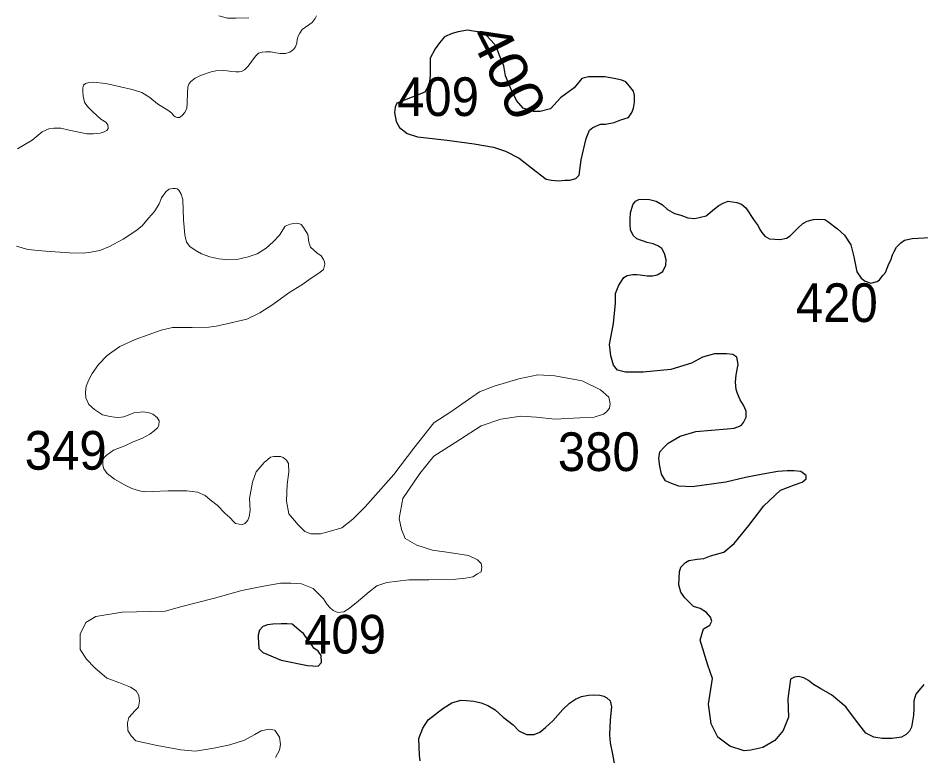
# Model space of a CAD drawing. Extents: x 445.4 to 500, y 8728.7 to 8784.
# Drawn here: x 490.993 to 494.73, y 8731.487 to 8734.54 of the extents above; entities that cross this region are included whole.
import ezdxf
from ezdxf.enums import TextEntityAlignment as Align

# ---------------------------------------------------------------- set-up
doc = ezdxf.new("R2010")
doc.units = 0
doc.header["$LTSCALE"] = 0.064
doc.layers.add('1', color=7, linetype='Continuous', lineweight=25)
doc.layers.add('2', color=7, linetype='Continuous', lineweight=13)
doc.layers.add('21', color=7, linetype='Continuous')
doc.layers.add('61', color=7, linetype='Continuous')

msp = doc.modelspace()

# ---------------------------------------------------------------- linework, layer by layer
at = {"layer": '1'}
for points in [[(492.7687, 8734.0344), (492.881, 8734.0204), (492.9618, 8734.0064), (493.0109, 8733.9889), (493.0671, 8733.9609), (493.1373, 8733.9048), (493.1794, 8733.8733), (493.2005, 8733.8698), (493.232, 8733.8663), (493.2566, 8733.8698), (493.2777, 8733.8698), (493.3022, 8733.8768), (493.3163, 8733.8908), (493.3233, 8733.9539), (493.3444, 8734.0414), (493.3584, 8734.0765), (493.3725, 8734.087), (493.404, 8734.101), (493.4251, 8734.101), (493.4602, 8734.108), (493.4883, 8734.1185), (493.5199, 8734.129), (493.5339, 8734.15), (493.5409, 8734.1676), (493.5444, 8734.1921), (493.5444, 8734.2201), (493.5409, 8734.2376), (493.5234, 8734.2586), (493.5093, 8734.2762), (493.4918, 8734.2832), (493.4602, 8734.2902), (493.4216, 8734.2972), (493.3935, 8734.2972), (493.3549, 8734.2972), (493.3268, 8734.2902), (493.2952, 8734.2516), (493.2391, 8734.2096), (493.1969, 8734.1641), (493.1548, 8734.1535), (493.1267, 8734.1535), (493.0846, 8734.1676), (493.0565, 8734.1991), (493.0355, 8734.2411), (493.0109, 8734.3007), (493.0039, 8734.3427), (492.9863, 8734.3848), (492.9723, 8734.4233), (492.9512, 8734.4478), (492.9302, 8734.4688), (492.8986, 8734.4829), (492.8775, 8734.4864), (492.853, 8734.4899), (492.8143, 8734.4829), (492.7898, 8734.4759), (492.7582, 8734.4618), (492.7371, 8734.4373), (492.7196, 8734.4128), (492.6985, 8734.3743), (492.6985, 8734.3497), (492.6985, 8734.3042), (492.695, 8734.2657), (492.6775, 8734.2341), (492.6248, 8734.2131), (492.5616, 8734.1886), (492.5546, 8734.1711), (492.5511, 8734.15), (492.5581, 8734.1115), (492.5722, 8734.087), (492.6037, 8734.0625), (492.6459, 8734.0484), (492.6845, 8734.0449)], [(492.1929, 8731.968), (492.1745, 8731.9938), (492.1649, 8732.0015), (492.1284, 8732.0323), (492.1072, 8732.0342), (492.0822, 8732.0342), (492.0475, 8732.0323), (492.0263, 8732.0304), (492.0058, 8732.0224), (491.9926, 8732.0084), (491.9878, 8731.9872), (491.987, 8731.9788), (491.9898, 8731.9322), (492.0062, 8731.9156), (492.0825, 8731.8837), (492.1919, 8731.861), (492.2361, 8731.8591), (492.2487, 8731.8741), (492.2475, 8731.9033), (492.2352, 8731.9204), (492.2176, 8731.9332), (492.2112, 8731.9443)]]:
    msp.add_lwpolyline(points, close=True, dxfattribs=at)
for points in [[(493.4805, 8733.4354), (493.5, 8733.4668), (493.5149, 8733.4757), (493.5373, 8733.4787), (493.5538, 8733.4787), (493.5687, 8733.4772), (493.5971, 8733.4742), (493.621, 8733.4742), (493.6389, 8733.4772), (493.6613, 8733.4921), (493.6748, 8733.5175), (493.6763, 8733.5398), (493.6688, 8733.5667), (493.6583, 8733.5861), (493.6419, 8733.598), (493.6225, 8733.6054), (493.5971, 8733.6114), (493.5538, 8733.6263), (493.5388, 8733.6412), (493.5283, 8733.6636), (493.5269, 8733.686), (493.5269, 8733.7098), (493.5283, 8733.7337), (493.5373, 8733.768), (493.5495, 8733.7822), (493.5629, 8733.7896), (493.5883, 8733.7911), (493.6063, 8733.7896), (493.6347, 8733.7822), (493.6601, 8733.7673), (493.681, 8733.7479), (493.7109, 8733.7315), (493.7363, 8733.724), (493.7661, 8733.7136), (493.7945, 8733.7106), (493.8408, 8733.7225), (493.8752, 8733.7509), (493.8931, 8733.7643), (493.9111, 8733.7747), (493.932, 8733.7822), (493.9679, 8733.7777), (493.9873, 8733.7703), (494.0052, 8733.7553), (494.0396, 8733.7031), (494.056, 8733.6808), (494.0635, 8733.6659), (494.0724, 8733.6524), (494.0844, 8733.6375), (494.1038, 8733.6271), (494.1471, 8733.6241), (494.174, 8733.6301), (494.189, 8733.639), (494.2069, 8733.6569), (494.2204, 8733.6703), (494.2413, 8733.6897), (494.2592, 8733.7002), (494.2861, 8733.7061), (494.304, 8733.7076), (494.3324, 8733.7061), (494.3444, 8733.6987), (494.3843, 8733.6686), (494.4142, 8733.6418), (494.4396, 8733.6015), (494.453, 8733.5523), (494.465, 8733.4903), (494.4829, 8733.4634), (494.4994, 8733.4515), (494.5233, 8733.444), (494.5487, 8733.45), (494.5591, 8733.4574), (494.5726, 8733.4753), (494.583, 8733.4873), (494.598, 8733.5231), (494.6054, 8733.538), (494.6129, 8733.5603), (494.6189, 8733.5738), (494.6293, 8733.5917), (494.6473, 8733.6096), (494.6622, 8733.6215), (494.6936, 8733.6275), (494.7683, 8733.6319)], [(493.9249, 8733.1511), (493.8757, 8733.1511), (493.8266, 8733.1374), (493.7801, 8733.1129), (493.6954, 8733.0856), (493.5806, 8733.0747), (493.5068, 8733.0747), (493.474, 8733.0829), (493.4576, 8733.1047), (493.4467, 8733.1429), (493.4413, 8733.1893), (493.4576, 8733.2765), (493.4657, 8733.3601), (493.4657, 8733.401), (493.4805, 8733.4354)], [(494.7425, 8731.7837), (494.7097, 8731.7428), (494.7015, 8731.7155), (494.7015, 8731.6828), (494.6988, 8731.6555), (494.696, 8731.6309), (494.6906, 8731.6064), (494.6824, 8731.59), (494.6687, 8731.5764), (494.6496, 8731.5655), (494.6113, 8731.56), (494.5703, 8731.56), (494.5348, 8731.5655), (494.502, 8731.5818), (494.4637, 8731.6309), (494.42, 8731.6909), (494.3599, 8731.74), (494.3162, 8731.7646), (494.2861, 8731.7837), (494.2643, 8731.8), (494.2451, 8731.8109), (494.2233, 8731.8164), (494.2069, 8731.8137), (494.1905, 8731.8055), (494.1795, 8731.7237), (494.1823, 8731.6473), (494.1604, 8731.5927), (494.1249, 8731.5518), (494.0757, 8731.5218), (494.0265, 8731.5109), (493.9992, 8731.5082), (493.9391, 8731.5273), (493.8899, 8731.5655), (493.8626, 8731.62), (493.8516, 8731.7018), (493.868, 8731.8082), (493.8489, 8731.8628), (493.8161, 8731.9664), (493.8298, 8732.0128), (493.8571, 8732.0291), (493.8653, 8732.0455), (493.8598, 8732.0619), (493.8434, 8732.081), (493.8161, 8732.0973), (493.7888, 8732.1055), (493.7533, 8732.141), (493.7369, 8732.1655), (493.7287, 8732.1955), (493.7309, 8732.2492), (493.7363, 8732.2683), (493.7555, 8732.2874), (493.7691, 8732.2956), (493.8046, 8732.3011), (493.832, 8732.3038), (493.8593, 8732.3147), (493.9139, 8732.3311), (493.9577, 8732.3665), (494.0178, 8732.4402), (494.0806, 8732.522), (494.149, 8732.5874), (494.2063, 8732.6093), (494.2391, 8732.6202), (494.2555, 8732.6338), (494.2555, 8732.6474), (494.2337, 8732.6638), (494.2036, 8732.6665), (494.1763, 8732.6665), (494.138, 8732.6638), (494.0752, 8732.6529), (494.0041, 8732.6393), (493.9221, 8732.6202), (493.7828, 8732.6011), (493.7281, 8732.6038), (493.6981, 8732.6147), (493.6735, 8732.6256), (493.6571, 8732.6529), (493.6489, 8732.6856), (493.6461, 8732.7184), (493.6489, 8732.7456), (493.668, 8732.7647), (493.6844, 8732.7811), (493.7336, 8732.8102), (493.7992, 8732.8292), (493.9277, 8732.8402), (493.9577, 8732.8429), (493.9796, 8732.8511), (493.9878, 8732.8565), (493.996, 8732.8674), (494.0069, 8732.8892), (494.0069, 8732.9138), (493.996, 8732.9383), (493.9823, 8732.9602), (493.9714, 8732.9874), (493.9659, 8733.0038), (493.9632, 8733.0338), (493.9659, 8733.0638), (493.9741, 8733.1074), (493.9687, 8733.1374), (493.9523, 8733.1484), (493.9249, 8733.1511)], [(492.6579, 8731.4668), (492.6552, 8731.4909), (492.6525, 8731.5599), (492.6686, 8731.6027), (492.6914, 8731.6362), (492.7518, 8731.6831), (492.7881, 8731.7072), (492.8257, 8731.7179), (492.8498, 8731.7166), (492.8793, 8731.7139), (492.9102, 8731.7072), (492.937, 8731.6965), (492.9679, 8731.6777), (493.0015, 8731.6483), (493.0431, 8731.6161), (493.0659, 8731.592), (493.0981, 8731.5759), (493.129, 8731.5759), (493.1531, 8731.5853), (493.1759, 8731.6054), (493.2068, 8731.6322), (493.2475, 8731.6793), (493.2757, 8731.7061), (493.3012, 8731.7221), (493.3254, 8731.7328), (493.3549, 8731.7395), (493.3764, 8731.7409), (493.4019, 8731.7395), (493.418, 8731.7342), (493.43, 8731.7275), (493.4435, 8731.7154), (493.4502, 8731.6913), (493.4461, 8731.6645), (493.4435, 8731.6351), (493.4421, 8731.6069), (493.4408, 8731.5748), (493.4435, 8731.5413), (493.4538, 8731.4944), (493.4629, 8731.4416)]]:
    msp.add_lwpolyline(points, dxfattribs=at)
at = {"layer": '2'}
for points in [[(491.1414, 8734.0851), (491.1708, 8734.0851), (491.2053, 8734.0765), (491.2785, 8734.061), (491.3061, 8734.061), (491.3338, 8734.0645), (491.3476, 8734.0679), (491.3614, 8734.0748), (491.3665, 8734.0834), (491.3648, 8734.0989), (491.3562, 8734.1092), (491.3355, 8734.1213), (491.3027, 8734.1523), (491.2803, 8734.1747), (491.2682, 8734.1919), (491.2622, 8734.2173), (491.2608, 8734.2369), (491.2615, 8734.2518), (491.2642, 8734.262), (491.2723, 8734.2687), (491.2859, 8734.2735), (491.3022, 8734.2748), (491.3564, 8734.2687), (491.4174, 8734.2559), (491.4662, 8734.2444), (491.5062, 8734.2315), (491.5394, 8734.2112), (491.5704, 8734.1858), (491.617, 8734.1565), (491.6291, 8734.1464), (491.6368, 8734.1366), (491.6436, 8734.1313), (491.652, 8734.129), (491.6611, 8734.129), (491.6725, 8734.1373), (491.6839, 8734.1495), (491.6915, 8734.1669), (491.693, 8734.1874), (491.6946, 8734.2307), (491.6964, 8734.2537), (491.7, 8734.2671), (491.7081, 8734.2779), (491.727, 8734.2913), (491.7486, 8734.3021), (491.7656, 8734.3083), (491.78, 8734.3128), (491.7926, 8734.3173), (491.8114, 8734.3218), (491.8429, 8734.3236), (491.859, 8734.3218), (491.8788, 8734.3191), (491.8941, 8734.3173), (491.9085, 8734.3173), (491.9183, 8734.3191), (491.93, 8734.3254), (491.9453, 8734.3415), (491.9764, 8734.3828), (491.9885, 8734.3949), (492.004, 8734.3983), (492.0195, 8734.4), (492.0402, 8734.4), (492.0609, 8734.3966), (492.0799, 8734.3932), (492.1006, 8734.3932), (492.1178, 8734.3983), (492.1334, 8734.4104), (492.142, 8734.4207), (492.1472, 8734.4362), (492.1489, 8734.4517), (492.1523, 8734.4655), (492.1592, 8734.4775), (492.1696, 8734.493), (492.1972, 8734.512), (492.211, 8734.5223), (492.2231, 8734.5378), (492.2282, 8734.5498)], [(491.9488, 8734.5412), (491.8953, 8734.5395), (491.8608, 8734.5395), (491.8246, 8734.5498)], [(490.9914, 8733.9991), (491.0517, 8734.0352), (491.0931, 8734.0697), (491.1207, 8734.0817), (491.1414, 8734.0851)], [(491.2865, 8732.9417), (491.2744, 8732.9689), (491.2725, 8732.9923), (491.2753, 8733.0166), (491.2865, 8733.0437), (491.2997, 8733.0699), (491.3269, 8733.1064), (491.3627, 8733.1435), (491.4152, 8733.181), (491.478, 8733.21), (491.5314, 8733.2296), (491.5858, 8733.2493), (491.6327, 8733.2596), (491.7143, 8733.2596), (491.7836, 8733.2614), (491.8136, 8733.2652), (491.8455, 8733.2717), (491.9408, 8733.2943), (491.994, 8733.3205), (492.0475, 8733.3549), (492.1147, 8733.4031), (492.1682, 8733.4358), (492.2062, 8733.4634), (492.2424, 8733.4875), (492.2579, 8733.4995), (492.2631, 8733.5219), (492.2614, 8733.5322), (492.2579, 8733.5408), (492.2476, 8733.5563), (492.2303, 8733.5684), (492.2042, 8733.5916), (492.1973, 8733.6123), (492.1921, 8733.645), (492.1749, 8733.6742), (492.1645, 8733.6863), (492.1559, 8733.6897), (492.1456, 8733.6915), (492.1352, 8733.6897), (492.1197, 8733.688), (492.099, 8733.6794), (492.0748, 8733.6415), (492.049, 8733.614), (492.0196, 8733.5882), (491.9834, 8733.5641), (491.9455, 8733.552), (491.8989, 8733.5417), (491.8644, 8733.54), (491.8247, 8733.5434), (491.7867, 8733.552), (491.7522, 8733.5641), (491.7264, 8733.5795), (491.7039, 8733.595), (491.6901, 8733.6123), (491.6832, 8733.6433), (491.6781, 8733.7052), (491.6755, 8733.7896), (491.6685, 8733.8113), (491.6581, 8733.8286), (491.6512, 8733.8338), (491.6434, 8733.8346), (491.6339, 8733.8346), (491.6174, 8733.832), (491.6044, 8733.8208), (491.5871, 8733.7958), (491.5768, 8733.7716), (491.5586, 8733.7396), (491.5326, 8733.712), (491.5067, 8733.6809), (491.4807, 8733.6602), (491.4288, 8733.6248), (491.3719, 8733.595), (491.3323, 8733.5778), (491.2943, 8733.5709), (491.2633, 8733.5674), (491.2063, 8733.5692), (491.1063, 8733.5761), (491.0338, 8733.5829), (490.9872, 8733.5967)], [(492.9095, 8732.8529), (492.992, 8732.8804), (493.0745, 8732.8926), (493.1387, 8732.8896), (493.2151, 8732.8804), (493.319, 8732.8865), (493.3771, 8732.8896), (493.4169, 8732.9018), (493.4291, 8732.9109), (493.4413, 8732.9262), (493.4444, 8732.9445), (493.4383, 8732.9719), (493.4046, 8733.0024), (493.3282, 8733.039), (493.2151, 8733.0604), (493.1448, 8733.0635), (493.0653, 8733.0482), (492.9645, 8733.0177), (492.9033, 8732.9933), (492.7841, 8732.9109), (492.7138, 8732.8651), (492.6313, 8732.7614), (492.5488, 8732.6516), (492.4296, 8732.5174), (492.3793, 8732.4676), (492.3334, 8732.431), (492.2815, 8732.4157), (492.2448, 8732.4066), (492.2051, 8732.4066), (492.1806, 8732.4157), (492.1531, 8732.4432), (492.1134, 8732.489), (492.1042, 8732.5408), (492.1073, 8732.611), (492.1134, 8732.6629), (492.1126, 8732.6971), (492.104, 8732.7105), (492.0906, 8732.7219), (492.0791, 8732.7258), (492.0667, 8732.7258), (492.0523, 8732.7258), (492.038, 8732.7229), (492.0265, 8732.7133), (492.0121, 8732.7019), (491.9789, 8732.6629), (491.9636, 8732.6201), (491.9514, 8732.553), (491.9544, 8732.5042), (491.95, 8732.4762), (491.9444, 8732.4631), (491.9387, 8732.4556), (491.9322, 8732.4491), (491.9228, 8732.4453), (491.9087, 8732.4463), (491.8937, 8732.4491), (491.8862, 8732.4566), (491.8693, 8732.4734), (491.8506, 8732.4903), (491.8168, 8732.5249), (491.7887, 8732.5473), (491.7672, 8732.5651), (491.7362, 8732.5782), (491.6922, 8732.5848), (491.65, 8732.5838), (491.6143, 8732.5838), (491.5497, 8732.581), (491.5184, 8732.5803), (491.4959, 8732.5841), (491.464, 8732.5934), (491.434, 8732.6093), (491.3918, 8732.6327), (491.3627, 8732.6561), (491.3487, 8732.6748), (491.344, 8732.6907), (491.344, 8732.7076), (491.3468, 8732.7188), (491.3581, 8732.731), (491.3881, 8732.7522), (491.435, 8732.77), (491.4697, 8732.7868), (491.5081, 8732.8018), (491.539, 8732.8186), (491.5569, 8732.8327), (491.5709, 8732.8448), (491.5765, 8732.8551), (491.5775, 8732.8738), (491.569, 8732.8879), (491.5512, 8732.9019), (491.5353, 8732.9075), (491.5119, 8732.9113), (491.4987, 8732.9103), (491.4725, 8732.9066), (491.449, 8732.8972), (491.4312, 8732.8907), (491.42, 8732.8888), (491.404, 8732.8879), (491.3928, 8732.8888), (491.374, 8732.8916), (491.3422, 8732.8991), (491.3093, 8732.9206), (491.2865, 8732.9417)], [(492.0584, 8731.4808), (492.0758, 8731.5111), (492.0802, 8731.535), (492.0758, 8731.5653), (492.0563, 8731.5935), (492.0324, 8731.5979), (491.9998, 8731.5914), (491.9737, 8731.5762), (491.9303, 8731.5523), (491.8695, 8731.5328), (491.8043, 8731.5198), (491.7283, 8731.5068), (491.6674, 8731.5133), (491.5697, 8731.5306), (491.4806, 8731.5502), (491.4609, 8731.5707), (491.4479, 8731.5924), (491.4457, 8731.6249), (491.4523, 8731.6466), (491.4783, 8731.6748), (491.4914, 8731.6899), (491.4957, 8731.7138), (491.4935, 8731.7376), (491.4827, 8731.7572), (491.4588, 8731.7723), (491.411, 8731.7918), (491.361, 8731.8092), (491.3111, 8731.8525), (491.2763, 8731.8872), (491.2502, 8731.9284), (491.2502, 8731.9913), (491.2741, 8732.039), (491.3154, 8732.065), (491.424, 8732.0824), (491.6017, 8732.0863), (491.6718, 8732.1051), (491.8066, 8732.1401), (491.9198, 8732.1724), (492.0017, 8732.1884), (492.0798, 8732.2018), (492.123, 8732.2018), (492.1661, 8732.1991), (492.2146, 8732.1803), (492.2577, 8732.1373), (492.2712, 8732.1157), (492.2847, 8732.0996), (492.2982, 8732.0888), (492.317, 8732.0808), (492.3413, 8732.0835), (492.3602, 8732.0942), (492.3925, 8732.1211), (492.4464, 8732.1669), (492.4788, 8732.1911), (492.5192, 8732.2045), (492.6102, 8732.2163), (492.6928, 8732.2163), (492.8059, 8732.2193), (492.8456, 8732.2224), (492.8762, 8732.2285), (492.8945, 8732.2407), (492.9098, 8732.2498), (492.9128, 8732.2681), (492.9098, 8732.2834), (492.8945, 8732.2986), (492.8578, 8732.3169), (492.7783, 8732.3292), (492.708, 8732.3383), (492.6439, 8732.3597), (492.5949, 8732.3871), (492.5797, 8732.4237), (492.5705, 8732.4695), (492.5858, 8732.5519), (492.6561, 8732.6556), (492.7138, 8732.7279), (492.8208, 8732.795), (492.9095, 8732.8529)]]:
    msp.add_lwpolyline(points, dxfattribs=at)

# ---------------------------------------------------------------- texts
at = {"layer": '21', "width": 0.95}
msp.add_text('409', height=0.16, dxfattribs=at).set_placement((492.9011, 8734.1349), align=Align.RIGHT)
for s, p in [('420', (494.2125, 8733.2826)), ('349', (491.0209, 8732.6717)), ('380', (493.2275, 8732.6661)), ('409', (492.1771, 8731.9111))]:
    msp.add_text(s, height=0.16, dxfattribs=at).set_placement(p)
at = {"layer": '61', "width": 1.15}
msp.add_text('400', height=0.16, rotation=297.086, dxfattribs=at).set_placement((492.9512, 8734.2856), align=Align.CENTER)

doc.saveas('drawing.dxf')
